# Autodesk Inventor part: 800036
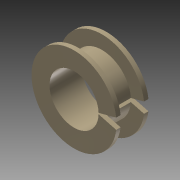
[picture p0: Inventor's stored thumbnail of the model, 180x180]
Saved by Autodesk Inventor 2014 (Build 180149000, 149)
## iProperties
Created: 2007-10
Part Number: 800036
Document SubType Name: Modeling
Designer: AL
Density: 8.47 g/cm^3
Mass: 2.09349 g
Surface Area: 7.3166 cm^2
Volume: 0.247165 cm^3
Material: Brass, Soft Yellow
Description: BUSHING 4 MM THICK
Appearance: Wheat
Component Category: Fasteners
Author: AL
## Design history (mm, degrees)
sketch "Sketch1"
  geometry: L1 (0, -3.85)-(0, 3.85) reference; L2 (-1.45, 0)-(8.7, 0) reference; L3 (4.18, -2.75)-(4.18, 2.75); L4 (4.18, 2.75)-(7.25, 2.75); L5 (7.25, 2.75)-(7.25, 2); L6 (7.25, 2)-(4.945, 2); L7 (4.945, 2)-(4.945, -2); L8 (4.945, -2)-(7.25, -2); L9 (7.25, -2)-(7.25, -2.75); L10 (7.25, -2.75)-(4.18, -2.75); 2 further points
  constraints: 16 end point, 6 parallel, 2 perpendicular, 1 collinear, 1 midpoint, 1 point on line
  dimensions: "d0" = 8.36 diameter of L3 L1; "d1" = 9.89 diameter of L7 L1; "d2" = 14.5 diameter of L5 L1; "d3" = 0.75 distance between parallel lines of L8 L10 (= d5); "d4" = 4 distance between parallel lines of L6 L8; "d5" = 0.75 distance between parallel lines of L4 L6
revolve "Revolution1" sketch "Sketch1" stored, may be unused: angle "d6" = 90 deg
sketch "Sketch3"
  geometry: L1 (-10.15, 0)-(10.15, 0) reference; L2 (0, 10.15)-(0, -10.15) reference; L3 (4.179, 0.101)-(7.193, 0.909); L4 (4.179, -0.101)-(7.193, -0.909); A1 r 7.25 centre (0, 0) between (7.193, 0.909) and (7.193, -0.909) reference; A2 r 4.18 centre (0, 0) between (4.179, -0.101) and (4.179, 0.101) reference; A3 r 4.18 centre (0, 0) between (4.179, -0.101) and (4.179, 0.101); A4 r 7.25 centre (0, 0) between (7.193, -0.909) and (7.193, 0.909)
  constraints: 8 point on circle, 4 end point, 2 centre point, 2 coincident
  dimensions: "d15" = 15 deg angle of L1 L4; "d16" = 30 deg angle of L3 L4; "d17" = 3.01401 horizontal distance of L3.start L3.end; "d18" = 3.01401 horizontal distance of L4.start L4.end
extrude "Extrusion2" cut sketch "Sketch3" stored distance "d19" = 10; taper "d20" = 0 deg
body "Solid1"
